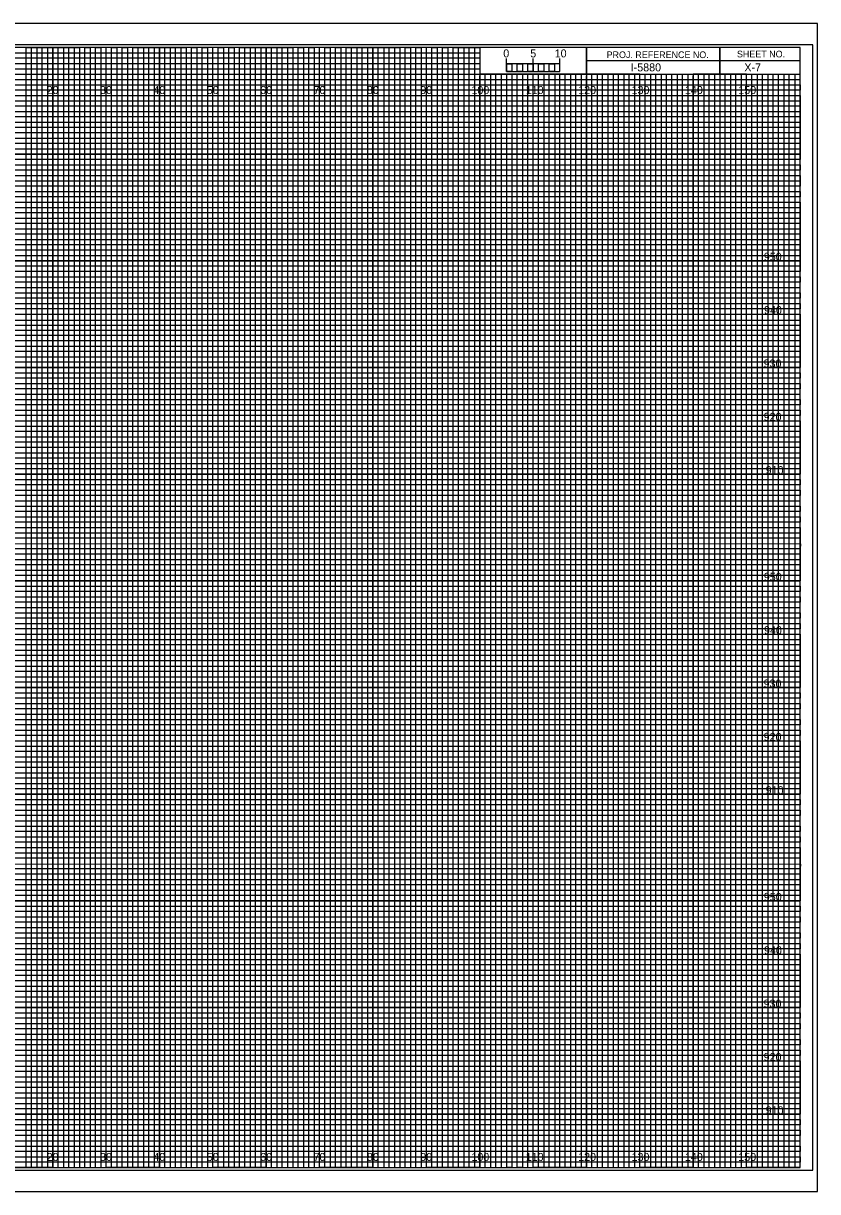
# Model space of a CAD drawing. Extents: x -13 to 323, y -4 to 3074.
# Drawn here: x 174.5 to 323.3, y 1095.5 to 1314.5 of the extents above; entities that cross this region are included whole.
import ezdxf

# ---------------------------------------------------------------- set-up
doc = ezdxf.new("R2010")
doc.units = 0
for name, color, linetype in [('Prop XS Bar Scale Labels', 7, 'Continuous'), ('Prop XS Elevation Labels', 7, 'Continuous'), ('Prop XS Offset Labels', 7, 'Continuous'), ('Prop XS Project Number', 7, 'Continuous'), ('Prop XS Sheet Number', 7, 'Continuous'), ('Sheet Cross Section CELL', 7, 'Continuous'), ('Sheet Cross Section Grid Major CELL', 7, 'Continuous'), ('Sheet Cross Section Grid Middle CELL', 7, 'Continuous'), ('Sheet Cross Section Grid Minor 1 CELL', 7, 'Continuous'), ('Sheet Cross Section Grid Minor 2 CELL', 7, 'Continuous'), ('Sheet Cross Section Scale CELL', 7, 'Continuous'), ('Sheet Cutting Line CELL', 7, 'Continuous'), ('Sheet DOT Grid CELL', 7, 'Continuous'), ('Sheet Plot Border Inside CELL', 7, 'Continuous'), ('Sheet Plot Border Outside CELL', 7, 'Continuous')]:
    doc.layers.add(name, color=color, linetype=linetype)

msp = doc.modelspace()

# ---------------------------------------------------------------- linework, layer by layer
at = {"layer": 'Sheet Cross Section CELL'}
for p, q in [((305, 1310), (305, 1305)), ((305, 1305), (305, 1310)), ((280, 1307.5), (280, 1305)), ((320, 1307.49), (280, 1307.49)), ((280, 1305), (320, 1305))]:
    msp.add_line(p, q, dxfattribs=at)
for points in [[(320, 1310), (0, 1310), (0, 1100), (320, 1100)], [(280, 1310), (260, 1310), (260, 1305.03), (280, 1305.03)], [(320, 1310), (280, 1310), (280, 1305), (320, 1305)]]:
    msp.add_lwpolyline(points, close=True, dxfattribs=at)
at = {"layer": 'Sheet Cross Section Grid Major CELL'}
for p, q in [((190, 1310), (180, 1310)), ((180, 1310), (180, 1100)), ((190, 1100), (190, 1310)), ((210, 1310), (200, 1310)), ((200, 1310), (200, 1100)), ((210, 1100), (210, 1310)), ((230, 1310), (220, 1310)), ((220, 1310), (220, 1100)), ((230, 1100), (230, 1310)), ((250, 1310), (240, 1310)), ((240, 1310), (240, 1100)), ((250, 1100), (250, 1310)), ((260, 1310), (260, 1100)), ((270, 1100), (270, 1305)), ((290, 1305), (280, 1305)), ((280, 1305), (280, 1100)), ((290, 1100), (290, 1305)), ((310, 1305), (300, 1305)), ((300, 1305), (300, 1100)), ((310, 1100), (310, 1305)), ((180, 1100), (170, 1100)), ((200, 1100), (190, 1100)), ((220, 1100), (210, 1100)), ((240, 1100), (230, 1100)), ((260, 1100), (250, 1100)), ((280, 1100), (270, 1100)), ((300, 1100), (290, 1100)), ((320, 1100), (310, 1100)), ((320, 1100), (320, 1100))]:
    msp.add_line(p, q, dxfattribs=at)
for points in [[(0, 1300), (320, 1300), (320, 1290), (0, 1290)], [(0, 1280), (320, 1280), (320, 1270), (0, 1270)], [(0, 1260), (320, 1260), (320, 1250), (0, 1250)], [(0, 1240), (320, 1240), (320, 1230), (0, 1230)], [(0, 1220), (320, 1220), (320, 1210), (0, 1210)], [(0, 1200), (320, 1200), (320, 1190), (0, 1190)], [(0, 1180), (320, 1180), (320, 1170), (0, 1170)], [(0, 1160), (320, 1160), (320, 1150), (0, 1150)], [(0, 1140), (320, 1140), (320, 1130), (0, 1130)], [(0, 1120), (320, 1120), (320, 1110), (0, 1110)]]:
    msp.add_lwpolyline(points, dxfattribs=at)
at = {"layer": 'Sheet Cross Section Grid Middle CELL'}
for points in [[(165, 1100), (175, 1100), (175, 1310), (185, 1310), (185, 1100), (195, 1100), (195, 1310), (205, 1310), (205, 1100), (215, 1100), (215, 1310), (225, 1310), (225, 1100), (235, 1100), (235, 1310), (245, 1310), (245, 1100), (255, 1100), (255, 1310), (259.93, 1310), (260, 1310), (260, 1305), (264.99, 1305), (264.99, 1100), (275, 1100), (275, 1305), (285, 1305), (285, 1100), (295, 1100), (295, 1305), (305, 1305), (305, 1100), (315, 1100), (315, 1305)], [(0, 1305), (275, 1305)], [(0, 1285), (320, 1285), (320, 1295), (0, 1295)], [(0, 1265), (320, 1265), (320, 1275), (0, 1275)], [(0, 1245), (320, 1245), (320, 1255), (0, 1255)], [(0, 1225), (320, 1225), (320, 1235), (0, 1235)], [(0, 1205), (320, 1205), (320, 1215), (0, 1215)], [(0, 1185), (320, 1185), (320, 1195), (0, 1195)], [(0, 1165), (320, 1165), (320, 1175), (0, 1175)], [(0, 1145), (320, 1145), (320, 1155), (0, 1155)], [(0, 1125), (320, 1125), (320, 1135), (0, 1135)], [(0, 1105), (320, 1105), (320, 1115), (0, 1115)]]:
    msp.add_lwpolyline(points, dxfattribs=at)
at = {"layer": 'Sheet Cross Section Grid Minor 1 CELL'}
for p, q in [((0, 1309), (260, 1309)), ((260, 1307.98), (0, 1307.98)), ((260, 1309), (260, 1307.98)), ((0, 1307), (260, 1307)), ((260, 1305.89), (0, 1305.89)), ((260, 1307), (260, 1305.89)), ((0, 1304), (320, 1304))]:
    msp.add_line(p, q, dxfattribs=at)
for points in [[(0, 1303), (270, 1303), (320, 1303), (320, 1302), (0, 1302)], [(0, 1301), (320, 1301), (320, 1299), (0, 1299)], [(0, 1298), (320, 1298), (320, 1297), (0, 1296.98)], [(0, 1296), (320, 1296), (320, 1294), (0, 1294)], [(0, 1293), (320, 1293), (320, 1292), (0, 1292)], [(0, 1291), (320, 1291), (320, 1289), (0, 1289)], [(0, 1288), (320, 1288), (320, 1287), (0, 1287)], [(0, 1286), (320, 1286), (320, 1284), (0, 1284)], [(0, 1283), (320, 1283), (320, 1282), (0, 1282)], [(0, 1281), (320, 1281), (320, 1279), (0, 1279)], [(0, 1278), (320, 1278), (320, 1277), (0, 1277)], [(0, 1276), (320, 1276), (320, 1273.95), (320, 1273), (320, 1272), (0, 1272)], [(0, 1274), (320, 1274), (320, 1273), (0, 1273)], [(0, 1271), (320, 1271), (320, 1269), (0, 1269.03)], [(0, 1269.03), (320, 1269), (320, 1268), (0, 1268)], [(0, 1267), (320, 1267), (320, 1266), (0, 1266)], [(0, 1264), (320, 1264), (320, 1263), (0, 1263)], [(0, 1262), (320, 1262), (320, 1261), (0, 1261)], [(-0.07, 1258.89), (320, 1258.89), (320, 1257.88), (-0.07, 1257.88)], [(0, 1257), (320, 1257), (320, 1256), (0, 1256)], [(0, 1254), (320, 1254), (320, 1253), (0, 1253)], [(0, 1252), (320, 1252), (320, 1251), (0, 1251)], [(0, 1249), (320, 1249), (320, 1248), (0, 1248)], [(0, 1247), (320, 1247), (320, 1246), (0, 1246)], [(0, 1244), (320, 1244), (320, 1243), (0, 1243)], [(0, 1242), (320, 1242), (320, 1241), (0, 1241)], [(0, 1239), (320, 1239), (319.99, 1237.98), (0, 1238)], [(0, 1237), (320, 1237), (320, 1236), (0, 1236)], [(0, 1234), (320, 1234), (320, 1233), (0, 1233)], [(0, 1232), (320, 1232), (320, 1231), (0, 1231)], [(0, 1229), (320, 1229), (320, 1228), (0, 1228)], [(0, 1227), (320, 1227), (320, 1226), (0, 1226)], [(0, 1224), (320, 1224), (320, 1223), (0, 1223)], [(0, 1222), (320, 1222), (320, 1221), (0, 1221)], [(0, 1219), (320, 1219), (320, 1218), (0, 1218)], [(0, 1216.99), (320.07, 1216.91), (320, 1216), (0, 1216)], [(0, 1214), (320, 1214), (320, 1213), (0, 1213)], [(0, 1212), (320, 1212), (320, 1211), (0, 1211)], [(0, 1209), (320, 1209), (320, 1208), (0, 1208)], [(0, 1207), (320, 1207), (320, 1206), (0, 1206)], [(0, 1204), (320, 1204), (320, 1203), (0, 1203)], [(0, 1202), (320, 1202), (320, 1201), (0, 1201)], [(0, 1199), (320, 1199), (320, 1198), (0, 1198)], [(0, 1197), (320, 1197), (320, 1196), (0, 1196)], [(0, 1194), (320, 1194), (320, 1193), (0, 1193)], [(0, 1192), (320, 1192), (320, 1191), (0, 1191)], [(0, 1189), (320, 1189), (320, 1188), (0, 1188)], [(0, 1187), (320, 1187), (320, 1186), (0, 1186)], [(0, 1184), (320, 1184), (320, 1183), (0, 1183)], [(0, 1182), (320, 1182), (320, 1181), (0, 1181)], [(0, 1179), (320, 1179), (319.99, 1177.98), (0, 1178)], [(0, 1177), (320, 1177), (320, 1176), (0, 1176)], [(0, 1174), (320, 1174), (320, 1173), (0, 1173)], [(0, 1172), (320, 1172), (320, 1171), (0, 1171)], [(0, 1169), (320, 1169), (320, 1168), (0, 1168)], [(0, 1167), (320, 1167), (320, 1166), (0, 1166)], [(0, 1164), (320, 1164), (320, 1163), (0, 1163)], [(0, 1162), (320, 1162), (320, 1161), (0, 1161)], [(0, 1159), (320, 1159), (320, 1158), (0, 1158)], [(0, 1156.99), (320.07, 1156.91), (320, 1156), (0, 1156)], [(0, 1154), (320, 1154), (320, 1153), (0, 1153)], [(0, 1152), (320, 1152), (320, 1151), (0, 1151)], [(0, 1149), (320, 1149), (320, 1148), (0, 1148)], [(0, 1147), (320, 1147), (320, 1146), (0, 1146)], [(0, 1144), (320, 1144), (320, 1143), (0, 1143)], [(0, 1142), (320, 1142), (320, 1141), (0, 1141)], [(0, 1139), (320, 1139), (320, 1138), (0, 1138)], [(0, 1137), (320, 1137), (320, 1136), (0, 1136)], [(0, 1134), (320, 1134), (320, 1133), (0, 1133)], [(0, 1132), (320, 1132), (320, 1131), (0, 1131)], [(0, 1129), (320, 1129), (320, 1128), (0, 1128)], [(0, 1127), (320, 1127), (320, 1126), (0, 1126)], [(0, 1124), (320, 1124), (320, 1123), (0, 1123)], [(0, 1122), (320, 1122), (320, 1121), (0, 1121)], [(0, 1119), (320, 1119), (320, 1118), (0, 1118)], [(0, 1117), (320, 1117), (320, 1116), (0, 1116)], [(0, 1114), (320, 1114), (320, 1113), (0, 1113)], [(0, 1112), (320, 1112), (320, 1111), (0, 1111)], [(0, 1109), (320, 1109), (320, 1108), (0, 1108)], [(0, 1107), (320, 1107), (320, 1106), (0, 1106)], [(0, 1104), (320, 1104), (320, 1103), (0, 1103)], [(0, 1102), (320, 1102), (320, 1101), (0, 1101)]]:
    msp.add_lwpolyline(points, dxfattribs=at)
at = {"layer": 'Sheet Cross Section Grid Minor 2 CELL'}
for p, q in [((267, 1305), (266.01, 1305)), ((266.01, 1305), (266.01, 1100)), ((267, 1100), (267, 1305)), ((269, 1305), (268, 1305)), ((268, 1305), (268, 1100)), ((269, 1100), (269, 1305)), ((266.01, 1100), (265, 1100)), ((268, 1100), (267, 1100))]:
    msp.add_line(p, q, dxfattribs=at)
for points in [[(175, 1100), (176, 1100), (176, 1310), (177, 1310), (177, 1100)], [(177, 1100), (178, 1100), (178, 1310), (179, 1310), (179, 1100)], [(180, 1100), (181, 1100), (181, 1310), (182, 1310), (182, 1100)], [(182, 1100), (183, 1100), (183, 1310), (184, 1310), (184, 1100)], [(185, 1100), (186, 1100), (186, 1310), (187, 1310), (187, 1100)], [(187, 1100), (188, 1100), (188, 1310), (189, 1310), (189, 1100)], [(190, 1100), (191, 1100), (191, 1310), (192, 1310), (192, 1100)], [(192, 1100), (193, 1100), (193, 1310), (194, 1310), (194, 1100)], [(195, 1100), (196, 1100), (196, 1310), (197, 1310), (197, 1100)], [(197, 1100), (198, 1100), (198, 1310), (199, 1310), (199, 1100)], [(200, 1100), (201, 1100), (201, 1310), (202, 1310), (202, 1100)], [(202, 1100), (203, 1100), (203, 1310), (204, 1310), (204, 1100)], [(205, 1100), (206, 1100), (206, 1310), (207, 1310), (207, 1100)], [(207, 1100), (208, 1100), (208, 1310), (209, 1310), (209, 1100)], [(210, 1100), (211, 1100), (211, 1310), (212, 1310), (212, 1100)], [(212, 1100), (213, 1100), (213, 1310), (214, 1310), (214, 1100)], [(215, 1100), (216, 1100), (216, 1310), (217, 1310), (217, 1100)], [(217, 1100), (218, 1100), (218, 1310), (219, 1310), (219, 1100)], [(220, 1100), (221, 1100), (221, 1310), (222, 1310), (222, 1100)], [(222, 1100), (223, 1100), (223, 1310), (224, 1310), (224, 1100)], [(225, 1100), (226, 1100), (226, 1310), (227, 1310), (227, 1100)], [(227, 1100), (228, 1100), (228, 1310), (229, 1310), (229, 1100)], [(230, 1100), (231, 1100), (231, 1310), (232, 1310), (232, 1100)], [(232, 1100), (233, 1100), (233, 1310), (234, 1310), (234, 1100)], [(235, 1100), (236, 1100), (236, 1310), (237, 1310), (237, 1100)], [(237, 1100), (238, 1100), (238, 1310), (239, 1310), (239, 1100)], [(240, 1100), (241, 1100), (241, 1310), (242, 1310), (242, 1100)], [(242, 1100), (243, 1100), (243, 1310), (244, 1310), (244, 1100)], [(245, 1100), (246, 1100), (246, 1310), (247, 1310), (247, 1100)], [(247, 1100), (248, 1100), (248, 1310), (249, 1310), (249, 1100)], [(250, 1100), (251, 1100), (251, 1310), (252, 1310), (252, 1100)], [(252, 1100), (253, 1100), (253, 1310), (254, 1310), (254, 1100)], [(255, 1100), (256, 1100), (256, 1310), (257, 1310), (257, 1100)], [(257, 1100), (258, 1100), (258, 1310), (259, 1310), (259, 1100)], [(260, 1100), (261, 1100), (261, 1305), (262.02, 1305), (262.02, 1100)], [(262, 1100), (263, 1100), (263, 1305), (263.99, 1305), (263.99, 1100)], [(270, 1100), (270.98, 1100), (270.98, 1305), (272, 1305), (272, 1100)], [(272, 1100), (273, 1100), (273, 1305), (274.05, 1305), (274.05, 1100)], [(275, 1100), (276, 1100), (276, 1305), (277, 1305), (277, 1100)], [(277, 1100), (278, 1100), (278, 1305), (279, 1305), (279, 1100)], [(280, 1100), (281, 1100), (281, 1305), (282, 1305), (282, 1100)], [(282, 1100), (283, 1100), (283, 1305), (284, 1305), (284, 1100)], [(285, 1100), (286, 1100), (286, 1305), (287, 1305), (287, 1100)], [(287, 1100), (288, 1100), (288, 1305), (289, 1305), (289, 1100)], [(290, 1100), (291, 1100), (291, 1305), (292, 1305), (292, 1100)], [(292, 1100), (293, 1100), (293, 1305), (294, 1305), (294, 1100)], [(295, 1100), (296, 1100), (296, 1305), (297, 1305), (297, 1100)], [(297, 1100), (298, 1100), (298, 1305), (299, 1305), (299, 1100)], [(300, 1100), (301, 1100), (301, 1305), (302, 1305), (302, 1100)], [(302, 1100), (303, 1100), (303, 1305), (304, 1305), (304, 1100)], [(305, 1100), (306, 1100), (306, 1305), (307, 1305), (307, 1100)], [(307, 1100), (308, 1100), (308, 1305), (309, 1305), (309, 1100)], [(310, 1100), (311, 1100), (311, 1305), (312, 1305), (312, 1100)], [(312, 1100), (313, 1100), (313, 1305), (314, 1305), (314, 1100)], [(315, 1100), (316, 1100), (316, 1305), (317, 1305), (317, 1100)], [(317, 1100), (318, 1100), (318, 1305), (319, 1305), (319, 1100)]]:
    msp.add_lwpolyline(points, dxfattribs=at)
at = {"layer": 'Sheet Cross Section Scale CELL'}
for p, q in [((265, 1305.49), (265, 1307.9)), ((265, 1306.9), (265, 1307.9)), ((270, 1305.49), (270, 1307.9)), ((275, 1305.49), (275, 1307.9)), ((275, 1306.9), (275, 1307.9))]:
    msp.add_line(p, q, dxfattribs=at)
for points in [[(275, 1306.9), (265, 1306.9), (265, 1305.49), (275, 1305.49)], [(265, 1306.9), (266, 1306.9), (266, 1305.49), (265, 1305.49)], [(267, 1306.9), (268, 1306.9), (268, 1305.49), (267, 1305.49)], [(269, 1306.9), (270, 1306.9), (270, 1305.49), (269, 1305.49)], [(271, 1306.9), (272, 1306.9), (272, 1305.49), (271, 1305.49)], [(273, 1306.9), (274, 1306.9), (274, 1305.49), (273, 1305.49)]]:
    msp.add_lwpolyline(points, close=True, dxfattribs=at)
at = {"layer": 'Sheet Cutting Line CELL'}
for p, q in [((323.3, 1314.5), (-13.4, 1314.5)), ((-13.4, 1095.5), (323.3, 1095.5))]:
    msp.add_line(p, q, dxfattribs=at)
at = {"layer": 'Sheet DOT Grid CELL'}
for p, q in [((180, 1100), (180, 1310)), ((190, 1100), (190, 1310)), ((200, 1100), (200, 1310)), ((210, 1100), (210, 1310)), ((220, 1100), (220, 1310)), ((230, 1100), (230, 1310)), ((240, 1100), (240, 1310)), ((250, 1100), (250, 1310)), ((260, 1100), (260, 1304.69)), ((270, 1100), (270, 1304.69)), ((280, 1100), (280, 1304.69)), ((290, 1100), (290, 1304.69)), ((300, 1100), (300, 1304.69)), ((310, 1100), (310, 1304.69)), ((0, 1300), (320, 1300)), ((0, 1290), (320, 1290)), ((0, 1280), (320, 1280)), ((0, 1270), (320, 1270)), ((0, 1260), (320, 1260)), ((0, 1250), (320, 1250)), ((0, 1240), (320, 1240)), ((0, 1230), (320, 1230)), ((0, 1220), (320, 1220)), ((0, 1210), (320, 1210)), ((0, 1200), (320, 1200)), ((0, 1190), (320, 1190)), ((0, 1180), (320, 1180)), ((0, 1170), (320, 1170)), ((0, 1160), (320, 1160)), ((0, 1150), (320, 1150)), ((0, 1140), (320, 1140)), ((0, 1130), (320, 1130)), ((0, 1120), (320, 1120)), ((0, 1110), (320, 1110))]:
    msp.add_line(p, q, dxfattribs=at)
at = {"layer": 'Sheet Plot Border Inside CELL'}
msp.add_lwpolyline([(-10.8, 1099.5), (322.4, 1099.5), (322.4, 1310.5), (-10.8, 1310.5)], close=True, dxfattribs=at)
at = {"layer": 'Sheet Plot Border Outside CELL'}
msp.add_lwpolyline([(-13.4, 1095.5), (323.3, 1095.5), (323.3, 1314.5), (-13.4, 1314.5)], close=True, dxfattribs=at)

# ---------------------------------------------------------------- texts
at = {"layer": 'Prop XS Bar Scale Labels'}
for s, p in [('5', (269.47, 1308.12)), ('10', (274.04, 1308.12))]:
    msp.add_text(s, height=1.5, dxfattribs=at).set_placement(p)
at = {"layer": 'Prop XS Elevation Labels'}
for s, p in [('950', (313.22, 1270)), ('940', (313.26, 1260)), ('930', (313.18, 1250)), ('920', (313.19, 1240)), ('910', (313.57, 1230)), ('950', (313.22, 1210)), ('940', (313.26, 1200)), ('930', (313.18, 1190)), ('920', (313.19, 1180)), ('910', (313.57, 1170)), ('950', (313.22, 1150)), ('940', (313.26, 1140)), ('930', (313.18, 1130)), ('920', (313.19, 1120)), ('910', (313.57, 1110))]:
    msp.add_text(s, height=1.5, dxfattribs=at).set_placement(p)
at = {"layer": 'Prop XS Offset Labels'}
for s, p in [('20', (178.86, 1301.25)), ('30', (188.86, 1301.25)), ('40', (198.86, 1301.25)), ('50', (208.86, 1301.25)), ('60', (218.86, 1301.25)), ('70', (228.86, 1301.25)), ('80', (238.86, 1301.25)), ('90', (248.86, 1301.25)), ('100', (258.44, 1301.25)), ('110', (268.62, 1301.25)), ('120', (278.44, 1301.25)), ('130', (288.44, 1301.25)), ('140', (298.44, 1301.25)), ('150', (308.44, 1301.25)), ('20', (178.86, 1101.25)), ('30', (188.86, 1101.25)), ('40', (198.86, 1101.25)), ('50', (208.86, 1101.25)), ('60', (218.86, 1101.25)), ('70', (228.86, 1101.25)), ('80', (238.86, 1101.25)), ('90', (248.86, 1101.25)), ('100', (258.44, 1101.25)), ('110', (268.62, 1101.25)), ('120', (278.44, 1101.25)), ('130', (288.44, 1101.25)), ('140', (298.44, 1101.25)), ('150', (308.44, 1101.25))]:
    msp.add_text(s, height=1.5, dxfattribs=at).set_placement(p)
at = {"layer": 'Prop XS Project Number'}
msp.add_text('I-5880', height=1.5, dxfattribs=at).set_placement((288.28, 1305.5))
at = {"layer": 'Prop XS Sheet Number'}
msp.add_text('X-7', height=1.5, dxfattribs=at).set_placement((309.57, 1305.5))
at = {"layer": 'Sheet Cross Section CELL'}
for s, p in [('PROJ. REFERENCE NO.', (283.77, 1307.99)), ('SHEET NO.', (308.19, 1308.12))]:
    msp.add_text(s, height=1.25, dxfattribs=at).set_placement(p)
at = {"layer": 'Sheet Cross Section Scale CELL'}
msp.add_text('0', height=1.5, dxfattribs=at).set_placement((264.41, 1308.12))

doc.saveas('drawing.dxf')
